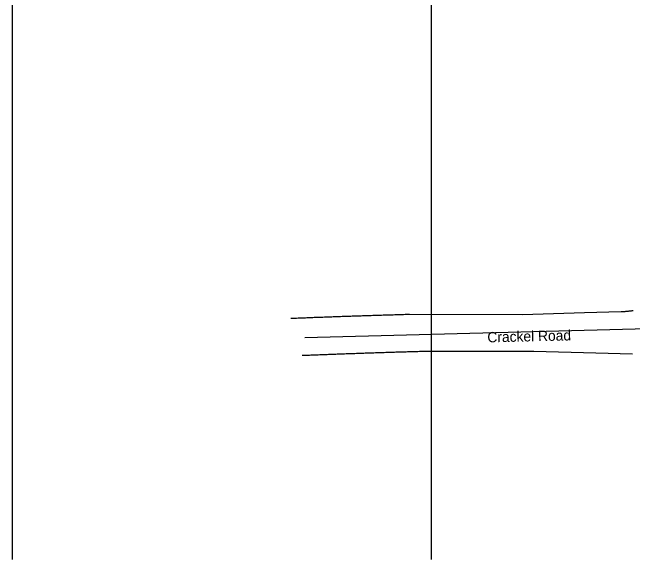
# Model space of a CAD drawing. Extents: x 2318076 to 2324211, y 613525 to 630327.
# Drawn here: x 2318412.8 to 2318832.9, y 614778.4 to 615148.8 of the extents above; entities that cross this region are included whole.
import ezdxf

# ---------------------------------------------------------------- set-up
doc = ezdxf.new("R2010")
doc.units = 0
for name, color, linetype in [('GE_P_CL_50', 7, 'Continuous'), ('GE_X_CL_50', 7, 'Continuous'), ('RS_Raster1', 7, 'Continuous'), ('SC_Scratch3', 7, 'Continuous')]:
    doc.layers.add(name, color=color, linetype=linetype)

msp = doc.modelspace()

# ---------------------------------------------------------------- linework, layer by layer
at = {"layer": 'GE_X_CL_50'}
msp.add_line((2318610.81, 614928.79), (2318880.9, 614935.75), dxfattribs=at)
at = {"layer": 'RS_Raster1'}
for p, q in [((2318825.16, 614946.02), (2318800.25, 614945.34)), ((2318832.89, 614917.47), (2318807.98, 614918.15))]:
    msp.add_line(p, q, dxfattribs=at)
for points in [[(2318681.73, 614944.29), (2318680.74, 614944.26), (2318679.74, 614944.23), (2318678.75, 614944.21), (2318677.76, 614944.18), (2318676.77, 614944.15), (2318675.77, 614944.12), (2318674.78, 614944.09), (2318673.79, 614944.06), (2318672.8, 614944.03), (2318671.8, 614944), (2318670.81, 614943.97), (2318669.82, 614943.95), (2318668.82, 614943.92), (2318667.83, 614943.89), (2318666.84, 614943.86), (2318665.85, 614943.83), (2318664.85, 614943.8), (2318663.86, 614943.76), (2318662.87, 614943.73), (2318661.88, 614943.7), (2318660.88, 614943.67), (2318659.89, 614943.64), (2318658.9, 614943.61), (2318657.9, 614943.58), (2318656.91, 614943.55), (2318655.92, 614943.52), (2318654.93, 614943.48), (2318653.93, 614943.45), (2318652.94, 614943.42), (2318651.95, 614943.39), (2318650.96, 614943.36), (2318649.96, 614943.32), (2318648.97, 614943.29), (2318647.98, 614943.26), (2318646.99, 614943.22), (2318645.99, 614943.19), (2318645, 614943.16), (2318644.01, 614943.12), (2318643.01, 614943.09), (2318642.02, 614943.06), (2318641.03, 614943.02), (2318640.04, 614942.99), (2318639.04, 614942.96), (2318638.05, 614942.92), (2318637.06, 614942.89), (2318636.07, 614942.85), (2318635.07, 614942.82), (2318634.08, 614942.78), (2318633.09, 614942.75), (2318632.1, 614942.71), (2318631.1, 614942.68), (2318630.11, 614942.64), (2318629.12, 614942.61), (2318628.12, 614942.57), (2318627.13, 614942.53), (2318626.14, 614942.5), (2318625.15, 614942.46), (2318624.15, 614942.43), (2318623.16, 614942.39), (2318622.17, 614942.35), (2318621.18, 614942.32), (2318620.18, 614942.28), (2318619.19, 614942.24), (2318618.2, 614942.21), (2318617.21, 614942.17), (2318616.21, 614942.13), (2318615.22, 614942.09), (2318614.23, 614942.05), (2318613.24, 614942.02), (2318612.25, 614941.98), (2318611.25, 614941.94), (2318610.26, 614941.9), (2318609.27, 614941.86), (2318608.28, 614941.82), (2318607.28, 614941.79), (2318606.29, 614941.75), (2318605.3, 614941.71), (2318604.31, 614941.67), (2318603.31, 614941.63), (2318602.32, 614941.59), (2318601.33, 614941.55)], [(2318800.25, 614945.34), (2318758.23, 614944.18), (2318681.73, 614944.29)], [(2318833.27, 614946.85), (2318832.85, 614946.79), (2318832.42, 614946.74), (2318832, 614946.68), (2318831.57, 614946.63), (2318831.14, 614946.58), (2318830.72, 614946.53), (2318830.29, 614946.48), (2318829.86, 614946.43), (2318829.44, 614946.39), (2318829.01, 614946.35), (2318828.58, 614946.3), (2318828.15, 614946.26), (2318827.73, 614946.22), (2318827.3, 614946.19), (2318826.87, 614946.15), (2318826.44, 614946.12), (2318826.02, 614946.08), (2318825.59, 614946.05), (2318825.16, 614946.02)], [(2318689.46, 614919.2), (2318688.47, 614919.18), (2318687.48, 614919.15), (2318686.48, 614919.12), (2318685.49, 614919.09), (2318684.5, 614919.06), (2318683.5, 614919.03), (2318682.51, 614919.01), (2318681.52, 614918.98), (2318680.53, 614918.95), (2318679.53, 614918.92), (2318678.54, 614918.89), (2318677.55, 614918.86), (2318676.56, 614918.83), (2318675.56, 614918.8), (2318674.57, 614918.77), (2318673.58, 614918.74), (2318672.58, 614918.71), (2318671.59, 614918.68), (2318670.6, 614918.65), (2318669.61, 614918.62), (2318668.61, 614918.59), (2318667.62, 614918.56), (2318666.63, 614918.52), (2318665.64, 614918.49), (2318664.64, 614918.46), (2318663.65, 614918.43), (2318662.66, 614918.4), (2318661.66, 614918.37), (2318660.67, 614918.33), (2318659.68, 614918.3), (2318658.69, 614918.27), (2318657.69, 614918.24), (2318656.7, 614918.2), (2318655.71, 614918.17), (2318654.72, 614918.14), (2318653.72, 614918.11), (2318652.73, 614918.07), (2318651.74, 614918.04), (2318650.75, 614918), (2318649.75, 614917.97), (2318648.76, 614917.94), (2318647.77, 614917.9), (2318646.77, 614917.87), (2318645.78, 614917.84), (2318644.79, 614917.8), (2318643.8, 614917.77), (2318642.8, 614917.73), (2318641.81, 614917.7), (2318640.82, 614917.66), (2318639.83, 614917.63), (2318638.83, 614917.59), (2318637.84, 614917.56), (2318636.85, 614917.52), (2318635.86, 614917.48), (2318634.86, 614917.45), (2318633.87, 614917.41), (2318632.88, 614917.38), (2318631.89, 614917.34), (2318630.89, 614917.3), (2318629.9, 614917.27), (2318628.91, 614917.23), (2318627.92, 614917.19), (2318626.92, 614917.16), (2318625.93, 614917.12), (2318624.94, 614917.08), (2318623.95, 614917.04), (2318622.95, 614917.01), (2318621.96, 614916.97), (2318620.97, 614916.93), (2318619.98, 614916.89), (2318618.98, 614916.85), (2318617.99, 614916.82), (2318617, 614916.78), (2318616.01, 614916.74), (2318615.01, 614916.7), (2318614.02, 614916.66), (2318613.03, 614916.62), (2318612.04, 614916.58), (2318611.05, 614916.54), (2318610.05, 614916.5), (2318609.06, 614916.46)], [(2318807.98, 614918.15), (2318765.96, 614919.31), (2318689.46, 614919.2)]]:
    msp.add_lwpolyline(points, dxfattribs=at)
at = {"layer": 'SC_Scratch3'}
for p, q in [((2318412.82, 614778.41), (2318412.82, 630327.22)), ((2318696.66, 614778.41), (2318696.66, 630327.22))]:
    msp.add_line(p, q, dxfattribs=at)

# ---------------------------------------------------------------- texts
at = {"layer": 'GE_P_CL_50'}
msp.add_text('Crackel Road', height=7, rotation=1.4386, dxfattribs=at).set_placement((2318734.59, 614925.39))

doc.saveas('drawing.dxf')
